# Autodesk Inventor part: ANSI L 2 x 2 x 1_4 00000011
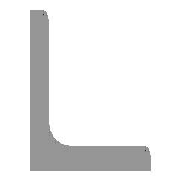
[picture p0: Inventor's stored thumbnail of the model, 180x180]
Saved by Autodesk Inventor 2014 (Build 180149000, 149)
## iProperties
IsCustomPart: 1
Created: 2007-02
Part Number: ANSI L 2 x 2 x 1_4 00000011
Material: Steel, Mild
Document SubType Name: Modeling
Standard: AISC
Designer: Autodesk, Inc.
Size Designation: L 2 x 2 x 1/4
Stock Number: L 2 x 2 x 1/4
Density: 7.86 g/cm^3
Description: Angle Steel
Standards Organization: ANSI
Language: en-US
Categories: <MemberInstance><Categories><Category DisplayName="Structural Shapes" InternalName="089c4875-fa83-4c05-b084-43b9cc11f5ed" Mnemonic="GRDR"><CategoryParameter Dis
Mass: 4291.52 g
Surface Area: 1807.63 cm^2
Volume: 545.995 cm^3
Appearance: Steel
_FrameMemberDoc: Frame Member File
_Version: 15.0.0
_CCFamilyMember: 11
_CCFamilyDisplayName: ANSI L (Equal angles) - Angle Steel
G_L: 37.887 in
G_W: 2.000 in
G_H: 2.000 in
+C03E24F3-4F1B-418A-9DED-6017E4CD22EF+CUTDETAIL1: Notch
+21F1AB7A-4E1C-46A2-8CCE-BEF31FB77FA0+CUTDETAIL2: Cut
+035F0972-CE3C-41F4-988E-BC34D1661BC5+CUTDETAIL3: Notch
+02A90EED-C822-4AE0-A167-DD75C78A2268+CUTDETAIL4: Notch
Author: Autodesk, Inc.
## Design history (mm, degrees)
node "Start plane"
node "End plane"
sketch "Sketch"
  geometry: L1 (50.8, 0)-(0, 0); L2 (0, 0)-(0, 50.8); L3 (0, 50.8)-(3.302, 50.8); L4 (6.35, 47.752)-(6.35, 12.7); L5 (12.7, 6.35)-(47.752, 6.35); L6 (50.8, 3.302)-(50.8, 0); L7 (0, -11.041)-(0, 31.538); L8 (-11.041, 0)-(31.538, 0); L9 (0, 63.926)-(0, -23.536) reference; L10 (-23.536, 0)-(63.926, 0) reference; A1 r 6.35 centre (12.7, 12.7) between (6.35, 12.7) and (12.7, 6.35); A2 r 3.048 centre (3.302, 47.752) between (6.35, 47.752) and (3.302, 50.8); A3 r 3.048 centre (47.752, 3.302) between (50.8, 3.302) and (47.752, 6.35); 3 further points
  constraints: 16 end point, 6 point on circle, 6 point on line, 6 tangent, 4 parallel, 3 centre point, 2 collinear, 1 equal radius, 1 horizontal, 1 perpendicular
  dimensions: "d0" = 50.8 distance between parallel lines of L6 L2 (= G_H); "d1" = 50.8 distance between parallel lines of L3 L1 (= G_H); "d2" = 6.35 distance between parallel lines of L2 L4 (= G_T); "d3" = 6.35 distance between parallel lines of L1 L5 (= G_T); "d10" = 0 distance between parallel lines of L7 L2 (computed from ex); "d11" = 0 distance between parallel lines of L8 L1 (computed from d10); "d14" = 6.35 radius of A1 (= G_IR); "d15" = 3.048 radius of A2 (= G_ER)
extrude "Body" new body sketch "Sketch" stored distance "d4" = 962.33018 (= G_L); taper "d5" = 0 deg
node "Driven Length"
  sketch "Sketch6"
    geometry: L1 (0, 0)-(10, 0) reference
    constraints: 2 end point, 1 horizontal
  workplane "Work Plane10"
  sketch "Sketch7"
    geometry: L1 (-2, 7.953)-(12, 7.953) reference; L2 (-2, 970.283)-(12, 970.283) reference
    dimensions: "d23" = 962.33018 distance between parallel lines of L1 L2 (derived)
workplane "Work Plane3"
workplane "Work Plane4"
workplane "Work Plane5"
split "Split1"
workplane "Work Plane6"
workplane "Work Plane7"
workplane "Work Plane8"
workplane "Work Plane9"
workplane "Work Plane11"
workplane "Work Plane12"
workplane "Work Plane13"
body "Solid1"
sketch "Sketch_1"
  geometry: L1 (50.8, 0)-(0, 0); L2 (0, 0)-(0, 50.8); L3 (0, 50.8)-(3.302, 50.8); L4 (6.35, 47.752)-(6.35, 12.7); L5 (12.7, 6.35)-(47.752, 6.35); L6 (50.8, 3.302)-(50.8, 0); A1 r 3.048 centre (3.302, 47.752) between (6.35, 47.752) and (3.302, 50.8); A2 r 6.35 centre (12.7, 12.7) between (6.35, 12.7) and (12.7, 6.35); A3 r 3.048 centre (47.752, 3.302) between (50.8, 3.302) and (47.752, 6.35)
  constraints: 12 end point, 6 point on circle, 3 centre point
extrude "Extrusion2" cut sketch "Sketch_1" stored distance "d24" = 3.302; taper "d25" = 0 deg
sketch "Sketch_2"
  geometry: L1 (50.8, 0)-(0, 0); L2 (0, 0)-(0, 50.8); L3 (0, 50.8)-(3.302, 50.8); L4 (6.35, 47.752)-(6.35, 12.7); L5 (12.7, 6.35)-(47.752, 6.35); L6 (50.8, 3.302)-(50.8, 0); A1 r 3.048 centre (3.302, 47.752) between (6.35, 47.752) and (3.302, 50.8); A2 r 6.35 centre (12.7, 12.7) between (6.35, 12.7) and (12.7, 6.35); A3 r 3.048 centre (47.752, 3.302) between (50.8, 3.302) and (47.752, 6.35)
  constraints: 12 end point, 6 point on circle, 3 centre point
extrude "Extrusion3" cut sketch "Sketch_2" stored distance "d26" = 3.302; taper "d27" = 0 deg
sketch "Sketch_3"
  geometry: L1 (50.8, 0)-(0, 0); L2 (0, 0)-(0, 50.8); L3 (0, 50.8)-(3.302, 50.8); L4 (6.35, 47.752)-(6.35, 12.7); L5 (12.7, 6.35)-(47.752, 6.35); L6 (50.8, 3.302)-(50.8, 0); A1 r 3.048 centre (3.302, 47.752) between (6.35, 47.752) and (3.302, 50.8); A2 r 6.35 centre (12.7, 12.7) between (6.35, 12.7) and (12.7, 6.35); A3 r 3.048 centre (47.752, 3.302) between (50.8, 3.302) and (47.752, 6.35)
  constraints: 12 end point, 6 point on circle, 3 centre point
extrude "Extrusion4" cut sketch "Sketch_3" stored distance "d28" = 3.302; taper "d29" = 0 deg
other parameters: "G_H" = 50.8 [user parameter; used in 2 equation terms], "G_T" = 6.35 [user parameter; used in 2 equation terms], "G_ER" = 3.048 [user parameter; used in 1 equation term], "G_IR" = 6.35 [user parameter; used in 1 equation term], "G_L" = 962.33018 (= d23) [user parameter; used in 1 equation term], "ex" = 0 [user parameter; used in 1 equation term], "G_OFFSET_START" = -7.95314 [user parameter; used in 1 equation term], "G_OFFSET_END" = 0 [user parameter; used in 1 equation term], "d12" = 7.95314 (= -G_OFFSET_START), "d13" = 970.28332 (= G_OFFSET_END + B_L), "B_L" = 970.28332 [user parameter; used in 1 equation term], "d22" = 90 deg
